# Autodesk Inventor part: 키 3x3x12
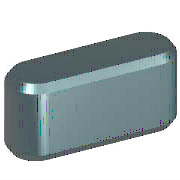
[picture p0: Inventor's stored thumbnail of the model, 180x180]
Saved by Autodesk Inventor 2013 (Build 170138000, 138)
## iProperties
Created: 2012-02
Part Number: 키 3x3x12
Material: 강철, 연강
Description: 키 및 해당 키홈
Document SubType Name: Modeling
Standard: KS B 1311
Designer: mduedu
Standards Organization: KS
Language: ko-KR
Size Designation: 3 x 3 x 12
Categories: <MemberInstance><Categories><Category DisplayName="샤프트 부품" InternalName="7f7aeb1f-a693-4053-b835-cee3144e0d98" Mnemonic="SHFT"><Category DisplayName="키" Interna
Density: 1 g/cm^3
IsCustomPart: 1
Author: mduedu
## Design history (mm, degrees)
workplane "Work Plane1"
workplane "Work Plane2"
sketch "스케치1"
  geometry: L1 (1.5, 1.5)-(10.5, 1.5); L2 (10.5, -1.5)-(1.5, -1.5); L3 (0, 9.4)-(0, -7.4) reference; L4 (-5, 0)-(30, 0) reference; L5 (12, 0)-(12, 7); A1 r 1.5 centre (1.5, 0) between (1.5, 1.5) and (1.5, -1.5); A2 r 1.5 centre (10.5, 0) between (10.5, -1.5) and (10.5, 1.5)
  constraints: 6 end point, 5 point on circle, 4 tangent, 3 point on line, 2 centre point, 1 horizontal, 1 parallel, 1 perpendicular
  dimensions: "d0" = 1.5 radius of A1 (= 0.5 x PB); "d13" = 1.5 radius of A2 (= 0.5 x PB); "d14" = 12 distance between parallel lines of L5 L3 (= NLG)
extrude "본체1" new body sketch "스케치1" taper "d3" = 0 deg; stored distance "d4" = 10
workplane "Work Plane3"
body "Solid1"
chamfer "모따기1" distance "d8" = 0.25 (= PHH); stored, may be unused: second distance "d9" = 0.25 (= PHH), angle "d15" = 45 deg
other parameters: "d1" = -1.8 (= -PNT), "d2" = 1.2 (= PH - PNT), "NLG" = 12 [user parameter; used in 3 equation terms], "PB" = 3 [user parameter; used in 2 equation terms], "PNT" = 1.8 [user parameter; used in 2 equation terms], "PH" = 3 [user parameter; used in 1 equation term], "PHH" = 0.25 [user parameter; used in 2 equation terms], "d10" = 0, "d16" = 0, "d17" = 0, "d18" = 0, "WDMIN" = 8 [user parameter], "PLB2" = 12 (= NLG) [user parameter], "PLB1" = 12 (= NLG) [user parameter], "RR" = 0.08 [user parameter], "PUEB" = 1.4 [user parameter]
